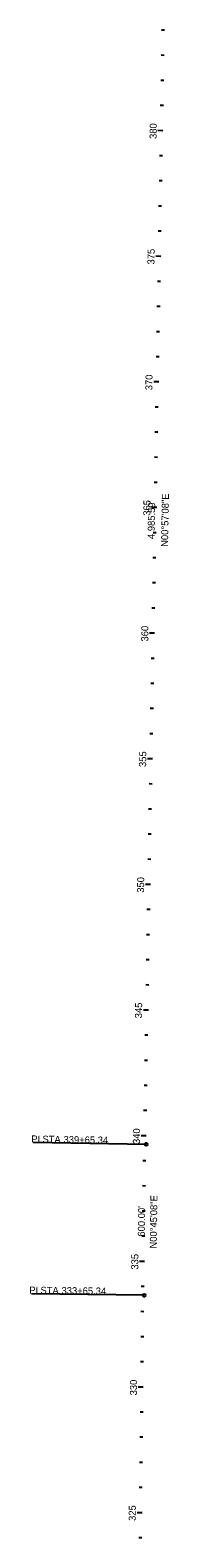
# Model space of a CAD drawing. Extents: x 1807668 to 1809726, y 297763 to 325145.
# Drawn here: x 1808281 to 1808835, y 312969 to 318969 of the extents above; entities that cross this region are included whole.
import ezdxf

# ---------------------------------------------------------------- set-up
doc = ezdxf.new("R2010")
doc.units = 0
for name, color, linetype in [('GE_P_Alignment_500_Bearings', 7, 'Continuous'), ('GE_P_Alignment_500_Cardinal_Points', 7, 'Continuous'), ('GE_P_Alignment_500_Distances', 7, 'Continuous'), ('GE_P_Alignment_500_Stations', 7, 'Continuous')]:
    doc.layers.add(name, color=color, linetype=linetype)

msp = doc.modelspace()

# ---------------------------------------------------------------- linework, layer by layer
at = {"layer": 'GE_P_Alignment_500_Cardinal_Points'}
for p, q in [((1808744.4, 314534.3), (1808294.4, 314541.7)), ((1808736.5, 313934.3), (1808286.5, 313940.2))]:
    msp.add_line(p, q, dxfattribs=at)
for centre in [(1808744.4, 314534.3), (1808736.5, 313934.3)]:
    msp.add_circle(centre, 6, dxfattribs=at)
at = {"layer": 'GE_P_Alignment_500_Stations'}
for p, q in [((1808818.1, 318968.3), (1808806.1, 318968.5)), ((1808816.4, 318868.3), (1808804.4, 318868.5)), ((1808814.7, 318768.3), (1808802.7, 318768.5)), ((1808813.1, 318668.3), (1808801.1, 318668.5)), ((1808811.4, 318568.4), (1808791.4, 318568.7)), ((1808809.8, 318468.4), (1808797.8, 318468.6)), ((1808808.1, 318368.4), (1808796.1, 318368.6)), ((1808806.4, 318268.4), (1808794.4, 318268.6)), ((1808804.8, 318168.4), (1808792.8, 318168.6)), ((1808803.1, 318068.4), (1808783.1, 318068.8)), ((1808801.4, 317968.4), (1808789.4, 317968.6)), ((1808799.8, 317868.5), (1808787.8, 317868.7)), ((1808798.1, 317768.5), (1808786.1, 317768.7)), ((1808796.5, 317668.5), (1808784.5, 317668.7)), ((1808794.8, 317568.5), (1808774.8, 317568.8)), ((1808793.1, 317468.5), (1808781.1, 317468.7)), ((1808791.5, 317368.5), (1808779.5, 317368.7)), ((1808789.8, 317268.5), (1808777.8, 317268.7)), ((1808788.2, 317168.6), (1808776.2, 317168.8)), ((1808786.5, 317068.6), (1808766.5, 317068.9)), ((1808784.8, 316968.6), (1808772.8, 316968.8)), ((1808783.2, 316868.6), (1808771.2, 316868.8)), ((1808781.5, 316768.6), (1808769.5, 316768.8)), ((1808779.8, 316668.6), (1808767.8, 316668.8)), ((1808778.2, 316568.6), (1808758.2, 316569)), ((1808776.5, 316468.6), (1808764.5, 316468.8)), ((1808774.9, 316368.7), (1808762.9, 316368.9)), ((1808773.2, 316268.7), (1808761.2, 316268.9)), ((1808771.5, 316168.7), (1808759.5, 316168.9)), ((1808769.9, 316068.7), (1808749.9, 316069)), ((1808768.2, 315968.7), (1808756.2, 315968.9)), ((1808766.5, 315868.7), (1808754.5, 315868.9)), ((1808764.9, 315768.7), (1808752.9, 315768.9)), ((1808763.2, 315668.8), (1808751.2, 315669)), ((1808761.6, 315568.8), (1808741.6, 315569.1)), ((1808759.9, 315468.8), (1808747.9, 315469)), ((1808758.2, 315368.8), (1808746.2, 315369)), ((1808756.6, 315268.8), (1808744.6, 315269)), ((1808754.9, 315168.8), (1808742.9, 315169)), ((1808753.3, 315068.8), (1808733.3, 315069.2)), ((1808751.6, 314968.9), (1808739.6, 314969.1)), ((1808749.9, 314868.9), (1808737.9, 314869.1)), ((1808748.3, 314768.9), (1808736.3, 314769.1)), ((1808746.6, 314668.9), (1808734.6, 314669.1)), ((1808744.9, 314568.9), (1808724.9, 314569.2)), ((1808743.5, 314468.9), (1808731.5, 314469.1)), ((1808742.2, 314368.9), (1808730.2, 314369.1)), ((1808740.9, 314268.9), (1808728.9, 314269.1)), ((1808739.6, 314168.9), (1808727.6, 314169.1)), ((1808738.3, 314069), (1808718.3, 314069.2)), ((1808736.9, 313969), (1808724.9, 313969.1)), ((1808735.9, 313869), (1808723.9, 313869.1)), ((1808734.9, 313769), (1808722.9, 313769.1)), ((1808733.9, 313669), (1808721.9, 313669.1)), ((1808733, 313569), (1808713, 313569.2)), ((1808732, 313469), (1808720, 313469.1)), ((1808731, 313369), (1808719, 313369.1)), ((1808730.1, 313269), (1808718.1, 313269.1)), ((1808729.1, 313169), (1808717.1, 313169.1)), ((1808728.1, 313069), (1808708.1, 313069.2)), ((1808727.2, 312969), (1808715.2, 312969.1))]:
    msp.add_line(p, q, dxfattribs=at)

# ---------------------------------------------------------------- texts
at = {"layer": 'GE_P_Alignment_500_Bearings'}
for s, rotation, p in [('N00°57\'08"E', 89.04778, (1808831.9, 316912.3)), ('N00°45\'08"E', 89.24778, (1808786.9, 314120))]:
    msp.add_text(s, height=28, rotation=rotation, dxfattribs=at).set_placement(p)
at = {"layer": 'GE_P_Alignment_500_Cardinal_Points'}
for s, rotation, p in [('PI', 359.04778, (1808286.2, 314542.3)), (' STA. ', 359.04778, (1808320.2, 314541.7)), ('339+65.34', 359.04778, (1808414.7, 314540.2)), ('PI', 359.24778, (1808278.3, 313940.7)), (' STA. ', 359.24778, (1808312.3, 313940.3)), ('333+65.34', 359.24778, (1808406.8, 313939.1))]:
    msp.add_text(s, height=28, rotation=rotation, dxfattribs=at).set_placement(p)
at = {"layer": 'GE_P_Alignment_500_Distances'}
for s, rotation, p in [("4,985.59'", 89.04778, (1808778.2, 316943.3)), ("600.00'", 89.24778, (1808739.1, 314167.5))]:
    msp.add_text(s, height=28, rotation=rotation, dxfattribs=at).set_placement(p)
at = {"layer": 'GE_P_Alignment_500_Stations'}
for s, rotation, p in [('380', 89.04778, (1808785.9, 318535.3)), ('375', 89.04778, (1808777.6, 318035.8)), ('370', 89.04778, (1808769.2, 317535.4)), ('365', 89.04778, (1808760.9, 317035.9)), ('360', 89.04778, (1808752.6, 316535.6)), ('355', 89.04778, (1808744.3, 316036.1)), ('350', 89.04778, (1808736, 315535.7)), ('345', 89.04778, (1808727.7, 315036.2)), ('340', 89.04778, (1808719.4, 314535.9)), ('335', 89.24778, (1808712.8, 314036.2)), ('330', 89.44778, (1808707.6, 313535.8)), ('325', 89.44778, (1808702.8, 313036.2))]:
    msp.add_text(s, height=28, rotation=rotation, dxfattribs=at).set_placement(p)

doc.saveas('drawing.dxf')
